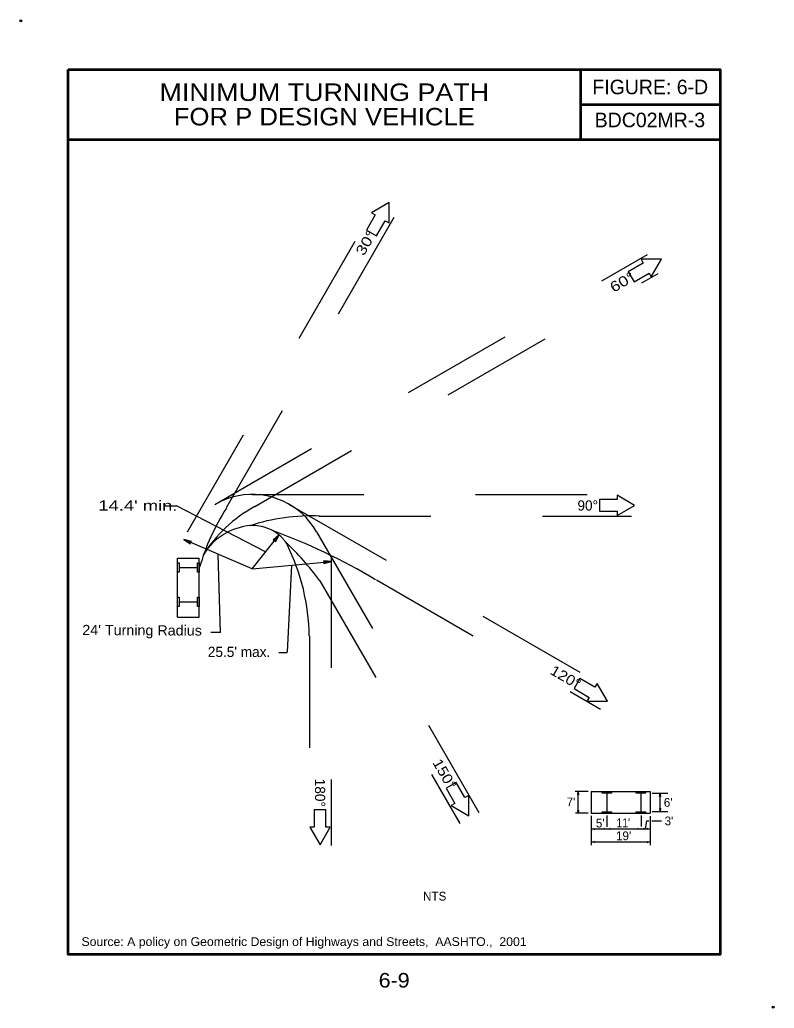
# Model space of a CAD drawing. Extents: x -4.063 to -3.388, y 3.968 to 4.852.
import ezdxf
from ezdxf.enums import TextEntityAlignment as Align

# ---------------------------------------------------------------- set-up
doc = ezdxf.new("R2010")
doc.units = 0
doc.header["$LTSCALE"] = 0.0036
doc.header["$PDMODE"] = 32
doc.header["$PDSIZE"] = 0.0018
doc.linetypes.add('LONG_DASHED', pattern=[7.5, 6, -1.5])
doc.layers.add('1', color=7, linetype='Continuous', lineweight=25)
doc.layers.add('24', color=7, linetype='Continuous', lineweight=25)

msp = doc.modelspace()

# ---------------------------------------------------------------- linework, layer by layer
at = {"layer": '1', "lineweight": 53}
for p, q in [((-3.561125, 4.80765), (-3.561125, 4.74515)), ((-3.561125, 4.7764), (-3.436125, 4.7764)), ((-4.019458, 4.74515), (-3.436125, 4.74515))]:
    msp.add_line(p, q, dxfattribs=at)
at = {"layer": '1', "linetype": 'LONG_DASHED'}
for p, q in [((-3.912675, 4.394158), (-3.739183, 4.694608)), ((-3.877675, 4.415858), (-3.722342, 4.684883)), ((-3.888267, 4.418567), (-3.501225, 4.642008)), ((-3.852542, 4.416725), (-3.4915, 4.625158)), ((-3.854933, 4.427492), (-3.515408, 4.427492)), ((-3.8216, 4.418567), (-3.533325, 4.252142)), ((-3.795117, 4.40805), (-3.515408, 4.40805)), ((-3.7972, 4.394158), (-3.652167, 4.14295)), ((-3.7841, 4.37235), (-3.7841, 4.113467)), ((-3.7436, 4.351075), (-3.543042, 4.2353)), ((-3.794283, 4.350225), (-3.669, 4.133225)), ((-3.803542, 4.300867), (-3.803542, 4.113467))]:
    msp.add_line(p, q, dxfattribs=at)
at = {"layer": '1'}
for p, q in [((-3.933442, 4.417225), (-3.9227, 4.4172)), ((-3.842825, 4.3761), (-3.9227, 4.4172)), ((-3.854933, 4.360825), (-3.915883, 4.387117)), ((-3.854933, 4.360825), (-3.830708, 4.391367)), ((-3.921675, 4.31755), (-3.921675, 4.370325)), ((-3.921675, 4.370325), (-3.902225, 4.370325)), ((-3.902225, 4.31755), (-3.902225, 4.370325)), ((-3.883292, 4.304067), (-3.885408, 4.373975)), ((-3.920292, 4.361992), (-3.903625, 4.361992)), ((-3.854933, 4.360825), (-3.783917, 4.367508)), ((-3.823183, 4.286483), (-3.819425, 4.364167)), ((-3.920292, 4.331433), (-3.903625, 4.331433)), ((-3.921675, 4.31755), (-3.902225, 4.31755)), ((-3.891758, 4.304142), (-3.883333, 4.304142)), ((-3.831017, 4.286075), (-3.823392, 4.286075)), ((-3.554275, 4.161717), (-3.565833, 4.161717)), ((-3.563167, 4.142217), (-3.563167, 4.16165)), ((-3.563142, 4.161442), (-3.56275, 4.158758)), ((-3.551433, 4.161717), (-3.49865, 4.161717)), ((-3.551433, 4.161717), (-3.551433, 4.142275)), ((-3.53755, 4.160333), (-3.53755, 4.143667)), ((-3.506983, 4.160333), (-3.506983, 4.143667)), ((-3.49865, 4.161717), (-3.49865, 4.142275)), ((-3.496875, 4.160233), (-3.482925, 4.160233)), ((-3.489808, 4.143867), (-3.489808, 4.160192)), ((-3.489808, 4.160075), (-3.489408, 4.1574)), ((-3.554275, 4.142275), (-3.565625, 4.142275)), ((-3.56315, 4.142242), (-3.56355, 4.144917)), ((-3.551433, 4.142275), (-3.49865, 4.142275)), ((-3.551433, 4.139992), (-3.551433, 4.113675)), ((-3.537442, 4.140108), (-3.537442, 4.130008)), ((-3.506883, 4.140108), (-3.506883, 4.130408)), ((-3.49865, 4.139667), (-3.49865, 4.113675)), ((-3.496875, 4.143883), (-3.482925, 4.143883)), ((-3.489808, 4.143983), (-3.4902, 4.146658)), ((-3.497267, 4.135358), (-3.488575, 4.135358)), ((-3.5513, 4.128267), (-3.49855, 4.128267)), ((-3.551167, 4.128258), (-3.548483, 4.128658)), ((-3.537383, 4.128267), (-3.540058, 4.127875)), ((-3.537333, 4.128258), (-3.53465, 4.128658)), ((-3.506883, 4.128267), (-3.509558, 4.127875)), ((-3.506892, 4.128208), (-3.504217, 4.1286)), ((-3.498608, 4.128267), (-3.501292, 4.127875)), ((-3.551358, 4.116567), (-3.498558, 4.116567)), ((-3.551333, 4.116567), (-3.54865, 4.116958)), ((-3.498608, 4.116517), (-3.501292, 4.116117))]:
    msp.add_line(p, q, dxfattribs=at)
at = {"layer": '1', "lineweight": 53}
msp.add_lwpolyline([(-4.019458, 4.80765), (-3.436125, 4.80765), (-3.436125, 4.015983), (-4.019458, 4.015983)], close=True, dxfattribs=at)
at = {"layer": '1'}
for points in [[(-3.75255, 4.663992), (-3.743533, 4.658783), (-3.735717, 4.672317), (-3.732342, 4.670358), (-3.732333, 4.6886), (-3.748133, 4.679483), (-3.744742, 4.677525)], [(-3.51835, 4.626658), (-3.513142, 4.617642), (-3.499617, 4.62545), (-3.497667, 4.622067), (-3.488542, 4.637858), (-3.506783, 4.637858), (-3.504825, 4.634475)], [(-3.544, 4.422817), (-3.544, 4.4124), (-3.528375, 4.4124), (-3.528375, 4.408492), (-3.512583, 4.417608), (-3.528375, 4.426725), (-3.528375, 4.422817)], [(-3.921683, 4.357825), (-3.921683, 4.366158), (-3.920292, 4.366158), (-3.920292, 4.357825)], [(-3.903625, 4.357825), (-3.903625, 4.366158), (-3.902225, 4.366158), (-3.902225, 4.357825)], [(-3.921675, 4.327267), (-3.921675, 4.3356), (-3.920283, 4.3356), (-3.920283, 4.327267)], [(-3.903625, 4.327267), (-3.903625, 4.3356), (-3.902225, 4.3356), (-3.902225, 4.327267)], [(-3.561633, 4.262767), (-3.566842, 4.253742), (-3.553308, 4.245933), (-3.555267, 4.242558), (-3.537033, 4.24255), (-3.546142, 4.25835), (-3.5481, 4.25495)], [(-3.672258, 4.169858), (-3.681283, 4.16465), (-3.673467, 4.151117), (-3.67685, 4.149175), (-3.661058, 4.14005), (-3.661058, 4.158283), (-3.66445, 4.156325)], [(-3.541717, 4.161717), (-3.533383, 4.161717), (-3.533383, 4.160325), (-3.541717, 4.160325)], [(-3.51115, 4.161733), (-3.502817, 4.161733), (-3.502817, 4.160333), (-3.51115, 4.160333)], [(-3.788875, 4.145342), (-3.799292, 4.145342), (-3.799292, 4.129717), (-3.8032, 4.129717), (-3.794083, 4.113925), (-3.784967, 4.129717), (-3.788875, 4.129717)], [(-3.541717, 4.143667), (-3.533383, 4.143667), (-3.533383, 4.142275), (-3.541717, 4.142275)], [(-3.51115, 4.143667), (-3.502817, 4.143667), (-3.502817, 4.142275), (-3.51115, 4.142275)]]:
    msp.add_lwpolyline(points, close=True, dxfattribs=at)
for points in [[(-3.563133, 4.159208), (-3.563567, 4.158692), (-3.563133, 4.161467)], [(-3.562758, 4.15875), (-3.563125, 4.159208), (-3.563133, 4.159208)], [(-3.489792, 4.157842), (-3.490233, 4.157325), (-3.489792, 4.160108)], [(-3.489417, 4.157383), (-3.489783, 4.157842), (-3.489792, 4.157842)], [(-3.563542, 4.144925), (-3.563167, 4.144467), (-3.56315, 4.144467)], [(-3.56315, 4.144467), (-3.562725, 4.144992), (-3.56315, 4.142208)], [(-3.490192, 4.146667), (-3.489817, 4.146208), (-3.489808, 4.146208)], [(-3.489808, 4.146208), (-3.489375, 4.146733), (-3.489808, 4.14395)], [(-3.50295, 4.128267), (-3.501825, 4.135358), (-3.49975, 4.135358)], [(-3.548933, 4.128258), (-3.548417, 4.127833), (-3.551192, 4.128258)], [(-3.548475, 4.128642), (-3.548933, 4.128267), (-3.548933, 4.128258)], [(-3.539608, 4.128267), (-3.540133, 4.1287), (-3.53735, 4.128267)], [(-3.540067, 4.127883), (-3.539608, 4.128258), (-3.539608, 4.128267)], [(-3.5351, 4.128258), (-3.534583, 4.127833), (-3.537358, 4.128258)], [(-3.534642, 4.128642), (-3.5351, 4.128267), (-3.5351, 4.128258)], [(-3.509108, 4.128267), (-3.509633, 4.1287), (-3.50685, 4.128267)], [(-3.509567, 4.127883), (-3.509108, 4.128258), (-3.509108, 4.128267)], [(-3.504667, 4.128208), (-3.504142, 4.127783), (-3.506925, 4.128208)], [(-3.504208, 4.128592), (-3.504667, 4.128217), (-3.504667, 4.128208)], [(-3.500842, 4.128267), (-3.501358, 4.1287), (-3.498583, 4.128267)], [(-3.5013, 4.127883), (-3.500842, 4.128258), (-3.500842, 4.128267)], [(-3.5491, 4.116567), (-3.548583, 4.116142), (-3.551358, 4.116567)], [(-3.548642, 4.11695), (-3.5491, 4.116575), (-3.5491, 4.116567)], [(-3.500842, 4.116517), (-3.501358, 4.116942), (-3.498583, 4.116517)], [(-3.5013, 4.116125), (-3.500842, 4.1165), (-3.500842, 4.116517)]]:
    msp.add_lwpolyline(points, dxfattribs=at)
at = {"layer": '1', "linetype": 'LONG_DASHED'}
for centre, radius, start, end in [((-3.854935, 4.360827), 0.066671, 29.99804, 171.65989), ((-3.712309, 4.308079), 0.197192, 147.10989, 164.00049), ((-3.792513, 4.307003), 0.125067, 118.68271, 147.99614), ((-3.802415, 4.236774), 0.171508, 87.26702, 108.55352), ((-3.851551, 4.344471), 0.055374, 94.81216, 147.05238), ((-3.854935, 4.360827), 0.038891, 48.59409, 91.4628), ((-4.034499, 3.861238), 0.56943, 59.37278, 69.74584), ((-3.854368, 4.364823), 0.035568, 29.30696, 44.99829), ((-4.002817, 4.196348), 0.259163, 36.42272, 46.80843), ((-3.992708, 4.298495), 0.188891, 0.71991, 26.30159)]:
    msp.add_arc(centre, radius, start, end, dxfattribs=at)
at = {"layer": '1'}
for p in [(-4.061917, 4.851233), (-3.388583, 3.968733)]:
    msp.add_point(p, dxfattribs=at)
at = {"layer": '24'}
for points in [[(-3.915883, 4.387117), (-3.910008, 4.38325), (-3.911042, 4.385025), (-3.909075, 4.385492), (-3.915883, 4.387117), (-3.915458, 4.38695), (-3.91015, 4.383408), (-3.91115, 4.385092), (-3.909367, 4.385517), (-3.915217, 4.386867), (-3.915025, 4.386742), (-3.910467, 4.383742), (-3.911183, 4.385108), (-3.909675, 4.385475), (-3.914925, 4.3867), (-3.9147, 4.386642), (-3.910717, 4.384), (-3.911242, 4.385108), (-3.910042, 4.385517), (-3.914083, 4.386375), (-3.913725, 4.386225), (-3.910967, 4.3843), (-3.911317, 4.385125), (-3.910408, 4.385483), (-3.913675, 4.386167), (-3.913342, 4.386), (-3.911242, 4.384625), (-3.911483, 4.385258), (-3.910825, 4.385492), (-3.913025, 4.385883), (-3.912717, 4.385708), (-3.911467, 4.384867), (-3.911558, 4.385267), (-3.911042, 4.38545), (-3.912533, 4.385675), (-3.911742, 4.385075), (-3.911758, 4.385375), (-3.911267, 4.38545), (-3.9123, 4.385608), (-3.911775, 4.385208), (-3.911942, 4.385508), (-3.911608, 4.3855), (-3.911967, 4.385442), (-3.911833, 4.38535)], [(-3.830708, 4.391367), (-3.835975, 4.3867), (-3.833983, 4.387233), (-3.83405, 4.385217), (-3.830708, 4.391367), (-3.830983, 4.391), (-3.835783, 4.386792), (-3.833892, 4.387325), (-3.83395, 4.385492), (-3.831125, 4.390792), (-3.831292, 4.390633), (-3.835383, 4.387017), (-3.833875, 4.387358), (-3.833908, 4.3858), (-3.831358, 4.39055), (-3.831475, 4.39035), (-3.835058, 4.387192), (-3.83385, 4.3874), (-3.833767, 4.38615), (-3.831892, 4.389825), (-3.832133, 4.389517), (-3.834708, 4.387358), (-3.833825, 4.387475), (-3.833708, 4.386508), (-3.8322, 4.389483), (-3.83245, 4.389208), (-3.834317, 4.387533), (-3.83365, 4.387608), (-3.8336, 4.386908), (-3.832642, 4.388925), (-3.832892, 4.388675), (-3.834033, 4.387683), (-3.833617, 4.387675), (-3.833583, 4.387125), (-3.832975, 4.388508), (-3.833758, 4.387892), (-3.833458, 4.387842), (-3.833517, 4.387342), (-3.8331, 4.3883), (-3.833617, 4.3879), (-3.833292, 4.387975), (-3.833383, 4.387658), (-3.833342, 4.388017), (-3.833467, 4.387917)], [(-3.783917, 4.367508), (-3.790933, 4.368075), (-3.789167, 4.367017), (-3.790667, 4.365658), (-3.783917, 4.367508), (-3.784375, 4.36745), (-3.790725, 4.368008), (-3.789042, 4.367008), (-3.7904, 4.365783), (-3.784617, 4.367408), (-3.78485, 4.367417), (-3.790292, 4.367867), (-3.789, 4.367017), (-3.79015, 4.365967), (-3.784958, 4.367408), (-3.785183, 4.367358), (-3.789942, 4.367758), (-3.788958, 4.367033), (-3.789808, 4.366108), (-3.78585, 4.367292), (-3.786242, 4.367258), (-3.789575, 4.367617), (-3.788883, 4.367058), (-3.7895, 4.366308), (-3.786308, 4.367283), (-3.786683, 4.367267), (-3.789183, 4.367458), (-3.788667, 4.367025), (-3.789133, 4.366508), (-3.787017, 4.367217), (-3.787367, 4.367217), (-3.788875, 4.367358), (-3.7886, 4.36705), (-3.788967, 4.36665), (-3.787542, 4.367167), (-3.788533, 4.367308), (-3.788367, 4.367058), (-3.788767, 4.36675), (-3.787783, 4.367108), (-3.788433, 4.367208), (-3.78815, 4.367025), (-3.788442, 4.366875), (-3.788158, 4.367092), (-3.788317, 4.367117)]]:
    msp.add_lwpolyline(points, dxfattribs=at)

# ---------------------------------------------------------------- texts
at = {"layer": '1'}
for s, height, width, p in [('MINIMUM TURNING PATH', 0.01562, 1.15, (-3.790292, 4.779525)), ('FOR P DESIGN VEHICLE', 0.01562, 1.1, (-3.790288, 4.75765)), ("11'", 0.007817, 0.9, (-3.522808, 4.129792)), ('6-9', 0.01303, 1.1, (-3.727792, 3.986342))]:
    msp.add_text(s, height=height, dxfattribs=dict(at, width=width)).set_placement(p, align=Align.CENTER)
for s, height, p in [('FIGURE: 6-D', 0.01303, (-3.498625, 4.785508)), ('BDC02MR-3', 0.01303, (-3.498929, 4.755992)), ("7'", 0.007817, (-3.569592, 4.148508)), ("6'", 0.007817, (-3.482592, 4.148067)), ("3'", 0.007817, (-3.481875, 4.131475)), ("5'", 0.007817, (-3.543367, 4.129533)), ("19'", 0.007817, (-3.522504, 4.118167))]:
    msp.add_text(s, height=height, dxfattribs=at).set_placement(p, align=Align.CENTER)
for s, rotation, width, p in [('30°', 60, 1.25, (-3.743417, 4.660287)), ('60°', 30, 1.25, (-3.511446, 4.619374)), ('120°', 330, 1.15, (-3.564038, 4.252872)), ('150°', 300, 1.15, (-3.679347, 4.162596))]:
    msp.add_text(s, height=0.009108, rotation=rotation, dxfattribs=dict(at, width=width)).set_placement(p, align=Align.RIGHT)
for s, rotation, width, p in [("14.4' min.", 359.826, 1.35, (-3.957126, 4.41298)), ("24' Turning Radius", 359.739, 1.05, (-3.953375, 4.30145))]:
    msp.add_text(s, height=0.009117, rotation=rotation, dxfattribs=dict(at, width=width)).set_placement(p, align=Align.CENTER)
msp.add_text('90°', height=0.009108, dxfattribs=at).set_placement((-3.545358, 4.41305), align=Align.RIGHT)
msp.add_text("25.5' max.", height=0.009117, rotation=359.978, dxfattribs=at).set_placement((-3.866589, 4.282088), align=Align.CENTER)
msp.add_text('180°', height=0.009108, rotation=270, dxfattribs=at).set_placement((-3.798642, 4.14795), align=Align.RIGHT)
msp.add_text('NTS', height=0.007817, dxfattribs=at).set_placement((-3.701983, 4.06415))
at = {"layer": '1', "width": 1.05}
msp.add_text('Source: A policy on Geometric Design of Highways and Streets,  AASHTO.,  2001', height=0.007817, dxfattribs=at).set_placement((-4.0076, 4.023508))

doc.saveas('drawing.dxf')
